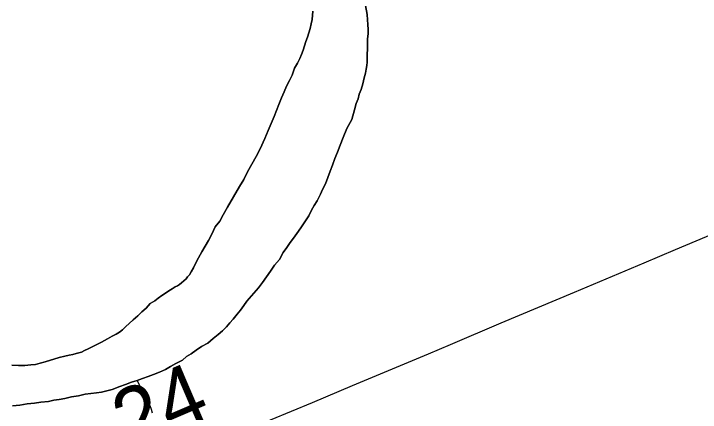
# Model space of a CAD drawing. Extents: x 0 to 64.8, y -5 to 22.
# Drawn here: x 6.975 to 7.614, y 20.159 to 20.529 of the extents above; entities that cross this region are included whole.
import ezdxf

# ---------------------------------------------------------------- set-up
doc = ezdxf.new("R2010")
doc.units = 0
for name, color, linetype in [('GM_X_County_Road', 7, 'Continuous'), ('GM_X_County_Road_Text', 7, 'Continuous'), ('GM_X_Major_River', 7, 'Continuous'), ('GM_X_Minor_River', 7, 'Continuous')]:
    doc.layers.add(name, color=color, linetype=linetype)

msp = doc.modelspace()

# ---------------------------------------------------------------- linework, layer by layer
at = {"layer": 'GM_X_County_Road'}
msp.add_lwpolyline([(6.75284, 19.95766), (6.80726, 19.98025), (6.85244, 19.99948), (6.87417, 20.00875), (6.91252, 20.02503), (6.96007, 20.04507), (7.02717, 20.07314), (7.077, 20.09418), (7.09765, 20.10284), (7.11602, 20.11045), (7.14006, 20.12064), (7.18592, 20.13989), (7.21406, 20.15158), (7.25305, 20.16789), (7.29026, 20.18365), (7.36081, 20.21315), (7.3815, 20.22168), (7.42837, 20.24172), (7.49656, 20.27044), (7.56137, 20.29757), (7.5906, 20.30984), (7.62895, 20.32611), (7.74942, 20.37642), (7.76671, 20.38376)], dxfattribs=at)
at = {"layer": 'GM_X_Major_River'}
for points in [[(7.30476, 20.51445), (7.30446, 20.51902), (7.30414, 20.5232), (7.30384, 20.52815), (7.30138, 20.54149)], [(7.30138, 20.54149), (7.30384, 20.52815), (7.30414, 20.5232), (7.30446, 20.51902), (7.30476, 20.51445)], [(7.2533, 20.53123), (7.2528, 20.52364), (7.25197, 20.51947), (7.25076, 20.51531), (7.24956, 20.51115), (7.24836, 20.50737), (7.24677, 20.50321), (7.24557, 20.49905), (7.24436, 20.49527), (7.24278, 20.49112), (7.2412, 20.48734), (7.23923, 20.48319), (7.23649, 20.4783), (7.23411, 20.47187), (7.23175, 20.46697), (7.229, 20.4617), (7.22664, 20.45641), (7.22427, 20.45075), (7.22189, 20.44471), (7.21952, 20.43905), (7.21753, 20.43338), (7.21476, 20.42696), (7.212, 20.42054), (7.20884, 20.41299), (7.20451, 20.40356), (7.20059, 20.39641), (7.19668, 20.38925), (7.19276, 20.38209), (7.18922, 20.37492), (7.18532, 20.36853), (7.17399, 20.34933), (7.17007, 20.34217), (7.16693, 20.33614), (7.16267, 20.33089), (7.15952, 20.3241), (7.15639, 20.31845), (7.15326, 20.31318), (7.15014, 20.3079), (7.147, 20.30225), (7.14426, 20.29698), (7.14229, 20.29283), (7.14033, 20.28906), (7.13877, 20.28643), (7.13684, 20.28456), (7.13567, 20.28268), (7.13142, 20.27894), (7.1295, 20.27745), (7.12758, 20.27634), (7.12528, 20.27524), (7.12259, 20.27338), (7.11952, 20.27153), (7.11644, 20.2693), (7.11298, 20.26708), (7.10952, 20.26485), (7.10644, 20.26224), (7.10221, 20.25965), (7.09834, 20.25553), (7.09449, 20.25217), (7.09063, 20.24843), (7.08638, 20.2447), (7.08253, 20.24134), (7.07944, 20.23835), (7.07635, 20.23536), (7.07365, 20.23313), (7.07058, 20.23127), (7.06675, 20.22943), (7.06252, 20.22684), (7.05677, 20.22389), (7.05255, 20.22168), (7.04833, 20.21947), (7.0445, 20.21763), (7.04105, 20.21616), (7.03837, 20.21469), (7.03569, 20.21397), (7.0334, 20.21325)], [(7.0334, 20.21325), (7.03569, 20.21397), (7.03837, 20.21469), (7.04105, 20.21616), (7.0445, 20.21763), (7.04833, 20.21947), (7.05255, 20.22168), (7.05677, 20.22389), (7.06252, 20.22684), (7.06675, 20.22943), (7.07058, 20.23127), (7.07365, 20.23313), (7.07635, 20.23536), (7.07944, 20.23835), (7.08253, 20.24134), (7.08638, 20.2447), (7.09063, 20.24843), (7.09449, 20.25217), (7.09834, 20.25553), (7.10221, 20.25965), (7.10644, 20.26224), (7.10952, 20.26485), (7.11298, 20.26708), (7.11644, 20.2693), (7.11952, 20.27153), (7.12259, 20.27338), (7.12528, 20.27524), (7.12758, 20.27634), (7.1295, 20.27745), (7.13142, 20.27894), (7.13567, 20.28268), (7.13684, 20.28456), (7.13877, 20.28643), (7.14033, 20.28906), (7.14229, 20.29283), (7.14426, 20.29698), (7.147, 20.30225), (7.15014, 20.3079), (7.15326, 20.31318), (7.15639, 20.31845), (7.15952, 20.3241), (7.16267, 20.33089), (7.16693, 20.33614), (7.17007, 20.34217), (7.17399, 20.34933), (7.18532, 20.36853), (7.18922, 20.37492), (7.19276, 20.38209), (7.19668, 20.38925), (7.20059, 20.39641), (7.20451, 20.40356), (7.20884, 20.41299), (7.212, 20.42054), (7.21476, 20.42696), (7.21753, 20.43338), (7.21952, 20.43905), (7.22189, 20.44471), (7.22427, 20.45075), (7.22664, 20.45641), (7.229, 20.4617), (7.23175, 20.46697), (7.23411, 20.47187), (7.23649, 20.4783), (7.23923, 20.48319), (7.2412, 20.48734), (7.24278, 20.49112), (7.24436, 20.49527), (7.24557, 20.49905), (7.24677, 20.50321), (7.24836, 20.50737), (7.24956, 20.51115), (7.25076, 20.51531), (7.25197, 20.51947), (7.2528, 20.52364), (7.2533, 20.53123)], [(6.97406, 20.16479), (6.98092, 20.16545), (6.98778, 20.16648), (6.99464, 20.16713), (7.00036, 20.16817), (7.0076, 20.16882), (7.01256, 20.16988), (7.01751, 20.17056), (7.02286, 20.17161), (7.02896, 20.17304), (7.03545, 20.17407), (7.04156, 20.17549), (7.04689, 20.17617), (7.05223, 20.17684), (7.0568, 20.17753), (7.06176, 20.17859), (7.06673, 20.18003), (7.074, 20.18258), (7.07935, 20.18439), (7.08471, 20.18659), (7.09007, 20.1884), (7.09504, 20.19022), (7.10039, 20.19203), (7.10536, 20.19385), (7.11072, 20.19605), (7.11647, 20.19862), (7.12107, 20.2012), (7.12607, 20.20416), (7.1322, 20.20711), (7.13606, 20.21046), (7.14028, 20.21306), (7.1449, 20.2164), (7.14989, 20.21974), (7.15565, 20.22307), (7.16066, 20.22717), (7.16528, 20.2309), (7.16952, 20.23425), (7.173, 20.238), (7.1761, 20.24175), (7.1792, 20.24512), (7.18308, 20.25), (7.18618, 20.25375), (7.18929, 20.25788), (7.19202, 20.26202), (7.20286, 20.27438), (7.20674, 20.27926), (7.21025, 20.28452), (7.21413, 20.28978), (7.21764, 20.29543), (7.22229, 20.30067), (7.22582, 20.30708), (7.22932, 20.31196), (7.23243, 20.31647), (7.23554, 20.3206), (7.23865, 20.32473), (7.24215, 20.33), (7.24604, 20.33564), (7.24956, 20.34128), (7.2523, 20.34656), (7.25465, 20.3507), (7.25738, 20.35522), (7.26052, 20.36125), (7.26249, 20.36578), (7.26524, 20.37105), (7.26723, 20.37672), (7.2696, 20.38276), (7.2716, 20.38843), (7.27397, 20.39448), (7.27635, 20.40052), (7.27873, 20.40694), (7.28151, 20.41412), (7.28506, 20.42242), (7.28976, 20.43071), (7.29218, 20.43979), (7.29379, 20.44546), (7.29539, 20.45), (7.29659, 20.45416), (7.29818, 20.45869), (7.29979, 20.46399), (7.30101, 20.46929), (7.30222, 20.47383), (7.30304, 20.47762), (7.30348, 20.48103), (7.30391, 20.48406), (7.30396, 20.48748), (7.30403, 20.49166), (7.30409, 20.49584), (7.30417, 20.50078), (7.30425, 20.50572), (7.3047, 20.51027), (7.30476, 20.51445)], [(7.30476, 20.51445), (7.3047, 20.51027), (7.30425, 20.50572), (7.30417, 20.50078), (7.30409, 20.49584), (7.30403, 20.49166), (7.30396, 20.48748), (7.30391, 20.48406), (7.30348, 20.48103), (7.30304, 20.47762), (7.30222, 20.47383), (7.30101, 20.46929), (7.29979, 20.46399), (7.29818, 20.45869), (7.29659, 20.45416), (7.29539, 20.45), (7.29379, 20.44546), (7.29218, 20.43979), (7.28976, 20.43071), (7.28506, 20.42242), (7.28151, 20.41412), (7.27873, 20.40694), (7.27635, 20.40052), (7.27397, 20.39448), (7.2716, 20.38843), (7.2696, 20.38276), (7.26723, 20.37672), (7.26524, 20.37105), (7.26249, 20.36578), (7.26052, 20.36125), (7.25738, 20.35522), (7.25465, 20.3507), (7.2523, 20.34656), (7.24956, 20.34128), (7.24604, 20.33564), (7.24215, 20.33), (7.23865, 20.32473), (7.23554, 20.3206), (7.23243, 20.31647), (7.22932, 20.31196), (7.22582, 20.30708), (7.22229, 20.30067), (7.21764, 20.29543), (7.21413, 20.28978), (7.21025, 20.28452), (7.20674, 20.27926), (7.20286, 20.27438), (7.19202, 20.26202), (7.18929, 20.25788), (7.18618, 20.25375), (7.18308, 20.25), (7.1792, 20.24512), (7.1761, 20.24175), (7.173, 20.238), (7.16952, 20.23425), (7.16528, 20.2309), (7.16066, 20.22717), (7.15565, 20.22307), (7.14989, 20.21974), (7.1449, 20.2164), (7.14028, 20.21306), (7.13606, 20.21046), (7.1322, 20.20711), (7.12607, 20.20416), (7.12107, 20.2012), (7.11647, 20.19862), (7.11072, 20.19605), (7.10536, 20.19385), (7.10039, 20.19203), (7.09504, 20.19022), (7.09007, 20.1884), (7.08471, 20.18659), (7.07935, 20.18439), (7.074, 20.18258), (7.06673, 20.18003), (7.06176, 20.17859), (7.0568, 20.17753), (7.05223, 20.17684), (7.04689, 20.17617), (7.04156, 20.17549), (7.03545, 20.17407), (7.02896, 20.17304), (7.02286, 20.17161), (7.01751, 20.17056), (7.01256, 20.16988), (7.0076, 20.16882), (7.00036, 20.16817), (6.99464, 20.16713), (6.98778, 20.16648), (6.98092, 20.16545), (6.97406, 20.16479)], [(7.0334, 20.21325), (7.03035, 20.21254), (7.02691, 20.21183), (7.02271, 20.21076), (7.01737, 20.2097), (7.00437, 20.20573), (6.99979, 20.20428), (6.99559, 20.20321), (6.99102, 20.20291), (6.98568, 20.20223), (6.9796, 20.20233), (6.97351, 20.20242)], [(6.97351, 20.20242), (6.9796, 20.20233), (6.98568, 20.20223), (6.99102, 20.20291), (6.99559, 20.20321), (6.99979, 20.20428), (7.00437, 20.20573), (7.01737, 20.2097), (7.02271, 20.21076), (7.02691, 20.21183), (7.03035, 20.21254), (7.0334, 20.21325)]]:
    msp.add_lwpolyline(points, dxfattribs=at)
at = {"layer": 'GM_X_Minor_River'}
msp.add_lwpolyline([(7.09007, 20.1884), (7.09412, 20.17997), (7.09597, 20.1769), (7.09708, 20.17499), (7.09819, 20.17307), (7.09892, 20.17116), (7.1004, 20.16809), (7.10187, 20.16503), (7.10296, 20.16159), (7.10404, 20.15816)], dxfattribs=at)

# ---------------------------------------------------------------- texts
at = {"layer": 'GM_X_County_Road_Text'}
msp.add_text('24', height=0.056818, rotation=23.19859, dxfattribs=at).set_placement((7.08319, 20.12104))

doc.saveas('drawing.dxf')
